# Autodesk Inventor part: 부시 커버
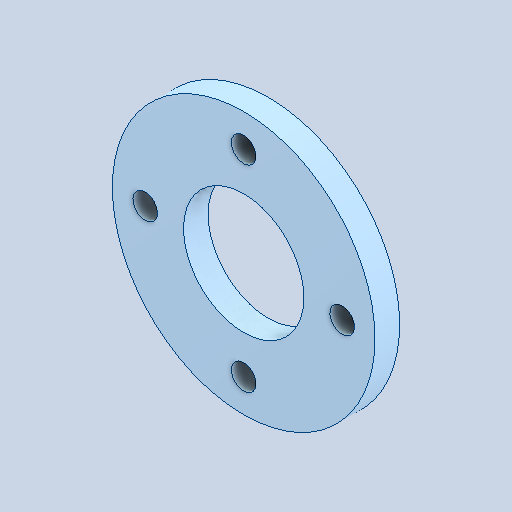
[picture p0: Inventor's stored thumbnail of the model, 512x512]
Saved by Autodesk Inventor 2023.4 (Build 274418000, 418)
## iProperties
Created: 2024-05
Part Number: 부시 커버
Material: 강철, 연강
Document SubType Name: Modeling
Designer: edu-40
Density: 7.85 g/cm^3
Appearance: 기본값
Author: jhkim
Sending System: Autodesk Inventor 2025
Preprocessor: ST-DEVELOPER v20
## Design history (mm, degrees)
feature "솔리드1"
node "솔리드2"
